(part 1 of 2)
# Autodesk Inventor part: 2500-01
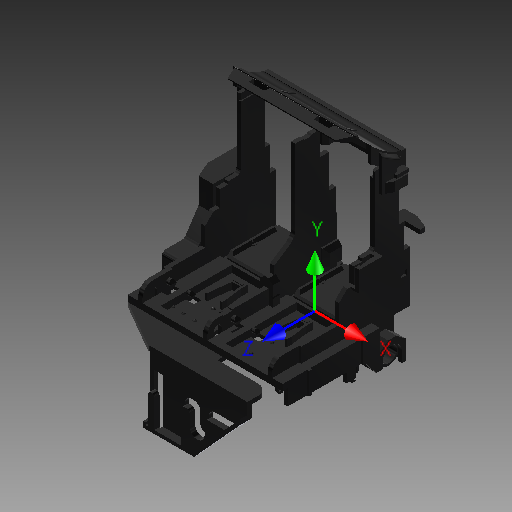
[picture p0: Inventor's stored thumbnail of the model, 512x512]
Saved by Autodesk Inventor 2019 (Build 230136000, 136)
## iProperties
Company: Autodesk Inc.
Created: 2006-01
Part Number: 2500-01
Document SubType Name: Modeling
Designer: Autodesk Inc.
Density: 1.06 g/cm^3
Mass: 41.9932 g
Surface Area: 433.717 cm^2
Volume: 39.6162 cm^3
Material: ABS Plastic
Appearance: Smooth - Black
Description: CARTRIDGE SEAT BLOCK
Author: Inventor
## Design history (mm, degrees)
sketch "Sketch1"
  geometry: L1 (0, 61.8)-(0, -3.3) reference; L2 (-6.86, 0)-(18.06, 0) reference; L3 (-3.3, 6)-(14.5, 6); L4 (14.5, 6)-(14.5, 52.5); L5 (14.5, 52.5)-(9.5, 52.5); L6 (9.5, 52.5)-(9.5, 50); L7 (9.5, 50)-(4, 50); L8 (4, 50)-(4, 21.9); L9 (4, 21.9)-(-0.5, 21.9); L10 (-0.5, 21.9)-(-0.5, 17.2); L11 (-0.5, 17.2)-(4, 17.2); L12 (4, 17.2)-(4, 13.3); L13 (4, 13.3)-(-3.3, 7.7); L14 (-3.3, 6)-(-3.3, 7.7)
  constraints: 24 end point, 6 parallel, 5 perpendicular, 1 collinear
  dimensions: "d2" = 6 distance between parallel lines of L3 L2; "d3" = 5 distance of L4.end L5.end; "d4" = 10.5 distance between parallel lines of L4 L8; "d5" = 4 distance between parallel lines of L8 L1; "d6" = 2.5 distance between parallel lines of L5 L7; "d8" = 52.5 distance between parallel lines of L5 L2; "d9" = 4.7 distance of L9.end L10.end; "d10" = 4.5 distance of L8.end L9.end; "d11" = 17.2 distance between parallel lines of L11 L2; "d12" = 17.8 distance between parallel lines of L4 L14; "d13" = 1.7 distance from line of L13.end L3; "d15" = 13.3 distance from line of L12.end L2
extrude "Extrusion1" new body sketch "Sketch1" stored distance "d16" = 74; taper "d17" = 0 deg
sketch "Sketch2"
  geometry: L1 (0, -46.5)-(74, -46.5) reference; L2 (37, -56.792)-(37, 10.66); L3 (27.5, -43.3)-(12.5, -43.3); L4 (12.5, -43.3)-(12.5, -9.3); L5 (12.5, -9.3)-(30.5, -9.3); L6 (30.5, -9.3)-(30.5, -36.3); L7 (27.5, -43.3)-(27.5, -38.5); L8 (29.7, -36.3)-(30.5, -36.3); A1 r 2.2 centre (29.7, -38.5) between (29.7, -36.3) and (27.5, -38.5); 1 further point
  constraints: 14 end point, 3 parallel, 3 perpendicular, 2 point on circle, 2 tangent, 1 centre point, 1 horizontal, 1 midpoint, 1 point on line
  dimensions: "d19" = 15 distance of L3.start L3.end; "d20" = 18 distance of L4.end L5.end; "d22" = 34 distance between parallel lines of L5 L3; "d23" = 27 distance between parallel lines of L5 L8; "d24" = 6.5 distance between parallel lines of L6 L2; "d25" = 3.2 distance between parallel lines of L1 L3; "d26" = 2.2 radius of A1
extrude "Extrusion2" cut sketch "Sketch2" distance "d27" = 3.3; taper "d28" = 0 deg
pattern_linear "Rectangular Pattern1" dims "d31" = 31
shell "Shell1" dims "d18" = 1.6
sketch "Sketch10"
  geometry: L1 (0, 0)-(74, 0) reference; L2 (0, -46.5)-(74, -46.5) reference; L3 (70, 0)-(4, 0); L4 (4, 0)-(4, 18.5); L5 (4, 18.5)-(70, 18.5); L6 (70, 18.5)-(70, 0); L7 (37, 31.5)-(37, -59.5) reference
  constraints: 8 end point, 2 parallel, 1 horizontal, 1 perpendicular, 1 point on line, 1 other
  dimensions: "d104" = 66 distance of L3.start L3.end; "d106" = 65 distance between parallel lines of L2 L5
extrude "Extrusion10" join sketch "Sketch10" distance "d107" = 2; taper "d108" = 0 deg
sketch "Sketch3"
  geometry: L1 (0, 0)-(74, 0) reference; L2 (1.6, -1.6)-(72.4, -1.6) reference; L3 (0, 0)-(23.5, 13.58); L4 (23.5, 13.58)-(70, 13.58); L5 (70, 13.58)-(70, 7.58); L6 (65, 2.58)-(45.5, 2.58); L7 (45.5, 2.58)-(45.5, 0); L8 (0, 0)-(45.5, 0); A1 r 5 centre (65, 7.58) between (65, 2.58) and (70, 7.58); 1 further point
  constraints: 12 end point, 3 perpendicular, 3 point on line, 2 point on circle, 2 tangent, 1 centre point, 1 collinear, 1 parallel
  dimensions: "d32" = 46.5 distance of L3.end L4.end; "d33" = 70 distance from line of L5 L1.start; "d34" = 11 distance of L4.end point (70, 2.58); "d35" = 13.58 distance between parallel lines of L1 L4; "d36" = 45.5 distance from line of L7 L1.start; "d37" = 5 radius of A1
extrude "Extrusion3" join sketch "Sketch3" distance "d38" = 2; taper "d39" = 0 deg
sketch "Sketch4"
  geometry: L1 (46.5, 2)-(0, 2) reference; L2 (0, 0)-(0, 2) reference; L3 (46.5, 0)-(0, 0) reference; L4 (46.5, 0)-(46.5, 2) reference; L5 (46.5, 2)-(46.5, -5.8); L6 (46.5, -5.8)-(24.5, -30); L7 (24.5, -30)-(0, -30); L8 (0, 0)-(0, -30)
  constraints: 8 end point, 2 perpendicular, 1 collinear
  dimensions: "d40" = 30 distance of L2.start L7.end; "d41" = 24.5 distance of L6.end L7.end; "d42" = 7.8 distance of L1.start L5.end
extrude "Extrusion4" join sketch "Sketch4" stored distance "d43" = 5.5; taper "d44" = 0 deg
sketch "Sketch5"
  geometry: L1 (-24.5, -30)-(-46.5, -5.8) reference; L2 (0, -30)-(-24.5, -30) reference; L3 (0, 0)-(0, -30) reference; L4 (-42.682, -10)-(-31, -10); L5 (-28, -13)-(-28, -18.5); L6 (-26, -20.5)-(-26, -20.5); L7 (-24, -18.5)-(-24, -13); L8 (-21, -10)-(-19.7, -10); L9 (-16.7, -13)-(-16.7, -30); L10 (-2, -30)-(-2, -7); L11 (-2, -7)-(-6, -7); L12 (-6, -7)-(-6, -30); L13 (-2, -30)-(-6, -30); A1 r 3 centre (-19.7, -13) between (-16.7, -13) and (-19.7, -10); A2 r 3 centre (-21, -13) between (-21, -10) and (-24, -13); A3 r 2 centre (-26, -18.5) between (-26, -20.5) and (-24, -18.5); A4 r 2 centre (-26, -18.5) between (-28, -18.5) and (-26, -20.5); A5 r 3 centre (-31, -13) between (-28, -13) and (-31, -10); 5 further points
  constraints: 20 end point, 14 point on line, 10 point on circle, 10 tangent, 5 centre point, 5 perpendicular, 3 collinear, 3 equal radius, 3 parallel
  dimensions: "d45" = 4 distance between parallel lines of L10 L12; "d46" = 23 distance of L10.start L10.end; "d47" = 20 distance of point (-16.7, -10) L9.end; "d48" = 7.3 distance of point (-24, -10) point (-16.7, -10); "d49" = 4 distance of point (-28, -20.5) point (-24, -20.5); "d50" = 10.7 distance between parallel lines of L9 L12; "d51" = 10.5 distance of point (-28, -10) point (-28, -20.5); "d52" = 2 distance between parallel lines of L3 L10; "d53" = 3 radius of A1; "d54" = 2 radius of A3
extrude "Extrusion5" cut sketch "Sketch5" distance "d55" = 3; taper "d56" = 0 deg
sketch "Sketch6"
  geometry: L1 (-42.682, -10)-(-31, -10) reference; L2 (-28, -13)-(-28, -18.5) reference; L3 (-24, -18.5)-(-24, -13) reference; L4 (-21, -10)-(-19.7, -10) reference; L5 (-16.7, -13)-(-16.7, -30) reference; L6 (-6, -30)-(-6, -7) reference; L7 (-6, -7)-(-2, -7) reference; L8 (-2, -7)-(-2, -30) reference; L9 (-46.5, -5.8)-(-46.5, 0) reference; L10 (-42.682, -10)-(-46.5, -5.8) reference; L11 (-40.519, -10)-(-39.065, -11.6); L12 (-39.065, -11.6)-(-31.1, -11.6); L13 (-29.6, -18.5)-(-29.6, -13.1); L14 (-22.4, -18.5)-(-22.4, -13.1); L15 (-18.3, -28.4)-(-16.7, -28.4); L16 (-18.3, -28.4)-(-18.3, -13.1); L17 (-19.8, -11.6)-(-20.9, -11.6); L18 (-27.997, -21.496)-(-28, -21.496); L19 (-24.5, -30)-(-42.682, -10) reference; L20 (-16.7, -30)-(-24.5, -30) reference; L21 (-2.5, -28.4)-(-2.5, -15); L22 (-4, -13.5)-(-4, -13.5); L23 (-5.5, -15)-(-5.5, -28.4); L24 (-6, -28.4)-(-6, -7.5); L25 (-6, -7.5)-(-2, -7.5); L26 (-2, -7.5)-(-2, -28.4); L27 (-2, -30)-(-6, -30) reference; L28 (-2, -28.4)-(-2.5, -28.4); L29 (-5.5, -28.4)-(-6, -28.4); A1 r 3 centre (-31, -13) between (-28, -13) and (-31, -10) reference; A2 r 2 centre (-26, -18.5) between (-28, -18.5) and (-24, -18.5) reference; A3 r 3 centre (-21, -13) between (-21, -10) and (-24, -13) reference; A4 r 3 centre (-19.7, -13) between (-16.7, -13) and (-19.7, -10) reference; A5 r 3.6 centre (-26, -18.5) between (-29.6, -18.5) and (-22.4, -18.5); A6 r 1.5 centre (-4, -15) between (-2.5, -15) and (-4, -13.5); A7 r 1.5 centre (-4, -15) between (-4, -13.5) and (-5.5, -15); A8 r 1.5 centre (-19.8, -13.1) between (-18.3, -13.1) and (-19.8, -11.6); A9 r 1.5 centre (-20.9, -13.1) between (-20.9, -11.6) and (-22.4, -13.1); A10 r 1.5 centre (-31.1, -13.1) between (-29.6, -13.1) and (-31.1, -11.6)
  constraints: 32 end point, 13 point on circle, 12 tangent, 10 perpendicular, 6 centre point, 5 parallel, 5 point on line, 4 equal radius, 3 collinear, 1 coincident
  dimensions: "d57" = 1.6 distance between parallel lines of L5 L16; "d58" = 1.6 distance between parallel lines of L17 L4 (= d57); "d59" = 1.6 distance between parallel lines of L3 L14 (= d57); "d60" = 1.6 distance between parallel lines of L13 L2 (= d57); "d61" = 1.6 distance between parallel lines of L1 L12 (= d57); "d62" = 1.6 distance between parallel lines of L19 L11 (= d57); "d63" = 1.6 distance between parallel lines of L20 L15 (= d57); "d64" = 0.5 distance between parallel lines of L6 L23; "d65" = 0.5 distance between parallel lines of L7 L25; "d66" = 16.5 distance between parallel lines of L27 L22; "d67" = 1.5 radius of A6
extrude "Extrusion6" cut sketch "Sketch6" extent not by distance; stored distance "d68" = 3; taper "d69" = 0 deg
sketch "Sketch7"
  geometry: L1 (2, -28.4)-(2, -7.5) reference; L2 (2, -7.5)-(6, -7.5) reference; L3 (6, -7.5)-(6, -28.4) reference; L4 (16.7, -28.4)-(16.7, -13) reference; L5 (19.7, -10)-(21, -10) reference; L6 (24, -13)-(24, -18.5) reference; L7 (28, -18.5)-(28, -13) reference; L8 (31, -10)-(40.519, -10) reference; L9 (0, -30)-(0, 2) reference; L10 (46.5, -5.8)-(24.5, -30) reference; L11 (46.5, 2)-(46.5, -5.8) reference; L12 (0, 2)-(46.5, 2) reference; L13 (16.7, -28.4)-(6, -28.4); L14 (2, -28.4)-(1.2, -28.4); L15 (1.2, -28.4)-(1.2, -27.4); L16 (1.2, -27.4)-(0, -27.4); L17 (0, -27.4)-(0, 2); L18 (40.519, -10)-(46.5, -3.421); A1 r 3 centre (19.7, -13) between (19.7, -10) and (16.7, -13) reference; A2 r 3 centre (21, -13) between (24, -13) and (21, -10) reference; A3 r 2 centre (26, -18.5) between (24, -18.5) and (28, -18.5) reference; A4 r 3 centre (31, -13) between (31, -10) and (28, -13) reference
  constraints: 12 end point, 2 collinear, 2 parallel, 2 perpendicular, 2 point on line
  dimensions: "d70" = 1 distance of L14.end L15.end; "d71" = 1.2 distance of L15.end L16.end
extrude "Extrusion7" cut sketch "Sketch7" distance "d72" = 3.5; taper "d73" = 0 deg
sketch "Sketch8"
  geometry: L1 (9.607, 52.5)-(16.5, 52.5); L2 (24.5, 20.5)-(29.5, 20.5); L3 (29.5, 20.5)-(34.682, 12.726); L4 (38.843, 10.5)-(75, 10.5); L5 (75, 10.5)-(75, 6.5); L6 (75, 6.5)-(74.4, 6.1); L7 (74.4, 6.1)-(74.4, 2.9); L8 (74.4, 2.9)-(75, 2.5); L9 (75, 2.5)-(75, -1.5); L10 (75, -1.5)-(63.5, -1.5); L11 (63.5, -1.5)-(63.5, -5.8); L12 (63.5, -5.8)-(47.5, -5.8); L13 (47.5, -5.8)-(47.5, -9.15); L14 (47.5, -9.15)-(36.5, -9.15); L15 (36.5, -9.15)-(36.5, -9.5); L16 (36.5, -9.5)-(9.607, -9.5); L17 (9.607, -9.5)-(9.607, 52.5); L18 (50.827, 4.5)-(44.324, 4.5); L19 (14.5, 52.5)-(14.5, 6) reference; L20 (14.5, 6)-(-3.3, 6) reference; L21 (9.5, 52.5)-(14.5, 52.5) reference; L22 (21.5, 45)-(20.9, 45); L23 (20.9, 45)-(20.9, 40.5); L24 (20.9, 40.5)-(21.5, 40.5); L25 (21.5, 47.5)-(21.5, 45); L26 (21.5, 40.5)-(21.5, 23.5); L27 (9.5, 66.08)-(11.5, 66.08) reference; L28 (14.5, -12.5)-(12.5, -12.5) reference; A1 r 5 centre (16.5, 47.5) between (21.5, 47.5) and (16.5, 52.5); A2 r 3 centre (24.5, 23.5) between (21.5, 23.5) and (24.5, 20.5); A3 r 5 centre (38.843, 15.5) between (34.682, 12.726) and (38.843, 10.5)
  constraints: 46 end point, 19 parallel, 7 perpendicular, 6 point on circle, 6 tangent, 4 collinear, 3 centre point, 1 horizontal, 1 vertical, 1 other
  dimensions: "d75" = 27 distance between parallel lines of L15 L11; "d76" = 3.2 distance of L6.end L7.end; "d77" = 4 distance of L8.end L5.end; "d78" = 12 distance between parallel lines of L10 L4; "d80" = 0.35 distance between parallel lines of L16 L14; "d82" = 20 distance between parallel lines of L16 L4; "d83" = 4.3 distance of L10.end L11.end; "d84" = 11.5 distance of L9.end L10.end; "d85" = 33 distance between parallel lines of L13 L19; "d86" = 60.5 distance between parallel lines of L19 L9; "d87" = 0.6 distance between parallel lines of L7 L5; "d89" = 30 distance between parallel lines of L16 L2; "d91" = 15 distance from line of L19 L2.end; "d92" = 0.6 distance of L23.end L24.end; "d93" = 7 distance between parallel lines of L19 L25; "d94" = 7.5 distance from line of L22.end L1; "d95" = 4.5 distance of L23.end L22.end; "d96" = 5 radius of A1; "d97" = 3 radius of A2; "d98" = 5 radius of A3; "d109" = 3 distance between parallel lines of L28 L16
extrude "Extrusion8" join sketch "Sketch8" stored distance "d99" = 2; taper "d100" = 0 deg
sketch "Sketch9"
  geometry: L1 (16.5, 49.5)-(9.5, 49.5); L2 (16.5, 45.5)-(9.5, 45.5); L3 (9.5, 49.5)-(9.5, 45.5); L4 (9.5, 66.08)-(9.5, 52.5) reference; A1 r 2 centre (16.5, 47.5) between (16.5, 45.5) and (16.5, 49.5); A2 r 5 centre (16.5, 47.5) between (21.5, 47.5) and (16.5, 52.5) reference
  constraints: 6 end point, 2 point on circle, 2 tangent, 1 centre point, 1 collinear, 1 concentric, 1 horizontal, 1 parallel, 1 perpendicular
  dimensions: "d101" = 4 distance between parallel lines of L2 L1
extrude "Extrusion9" cut sketch "Sketch9" stored distance "d102" = 10; taper "d103" = 0 deg
sketch "Sketch11"
  geometry: L1 (-33.1, 9.2)-(-40.9, 9.2); L2 (-40.9, 9.2)-(-40.9, 14.8); L3 (-40.9, 14.8)-(-33.1, 14.8); L4 (-33.1, 14.8)-(-33.1, 9.2); L5 (-37, 81.266)-(-37, -32.596) reference; 1 further point
  constraints: 8 end point, 2 parallel, 1 horizontal, 1 perpendicular, 1 other
  dimensions: "d110" = 7.8 distance of L2.end L3.end; "d111" = 5.6 distance of L1.end L2.end; "d112" = 2.2 distance from line of L1 point (-38, 7)
extrude "Extrusion11" cut sketch "Sketch11" distance "d113" = 2; taper "d114" = 0 deg
sketch "Sketch12"
  geometry: L1 (-40.9, 14.8)-(-38, 14.8) reference; L2 (-34, 29.3)-(-40, 29.3); L3 (-40, 29.3)-(-40, 32.8); L4 (-40, 32.8)-(-34, 32.8); L5 (-34, 32.8)-(-34, 29.3); L6 (-37, 81.266)-(-37, -32.596) reference
  constraints: 8 end point, 2 parallel, 1 horizontal, 1 perpendicular, 1 other
  dimensions: "d115" = 6 distance of L2.start L2.end; "d116" = 3.5 distance of L2.end L3.end; "d117" = 14.5 distance between parallel lines of L2 L1
extrude "Extrusion12" join sketch "Sketch12" distance "d118" = 11.2; taper "d119" = 0 deg
chamfer "Chamfer1" distance "d120" = 2; stored, may be unused: second distance "d121" = 2, angle "d122" = 45 deg
sketch "Sketch13"
  geometry: L1 (0, 0)-(0, -22) reference; L2 (-0.8, -10.7)-(2.8, -10.7); L3 (2.8, -10.7)-(4.5, -12.6); L4 (4.5, -12.6)-(4.5, -18.2); L5 (4.5, -18.2)-(-2.5, -18.2); L6 (-2.5, -18.2)-(-2.5, -12.6); L7 (-2.5, -12.6)-(-0.8, -10.7); L8 (1, -76.1)-(1, 57.6) reference; L9 (38, -22)-(2, -22) reference
  constraints: 12 end point, 3 perpendicular, 1 parallel, 2 other
  dimensions: "d123" = 7.5 distance between parallel lines of L5 L2; "d124" = 7 distance of L4.end L5.end; "d125" = 5.6 distance of L3.end L4.end; "d126" = 3.6 distance of L2.start L2.end; "d127" = 3.8 distance between parallel lines of L9 L5
extrude "Extrusion13" join sketch "Sketch13" distance "d128" = 7.8; taper "d129" = 0 deg
chamfer "Chamfer2" distance "d130" = 1.8; stored, may be unused: second distance "d131" = 2, angle "d132" = 45 deg
sketch "Sketch14"
  geometry: L1 (4.5, -18.2)-(2, -18.2) reference; L2 (4.5, -12.6)-(4.5, -18.2) reference; L3 (2.8, -10.7)-(4.5, -12.6) reference; L4 (2, -10.7)-(2.8, -10.7) reference; L5 (-0.8, -10.7)-(0, -10.7) reference; L6 (-2.5, -12.6)-(-0.8, -10.7) reference; L7 (-2.5, -18.2)-(-2.5, -12.6) reference; L8 (0, -18.2)-(-2.5, -18.2) reference; L9 (-0.353, -11.7)-(2.353, -11.7); L10 (2.353, -11.7)-(3.5, -12.982); L11 (3.5, -12.982)-(3.5, -17.2); L12 (3.5, -17.2)-(-1.5, -17.2); L13 (-1.5, -17.2)-(-1.5, -12.982); L14 (-1.5, -12.982)-(-0.353, -11.7)
  constraints: 12 end point, 8 parallel, 1 perpendicular
  dimensions: "d133" = 1 distance between parallel lines of L4 L9; "d134" = 1 distance between parallel lines of L3 L10; "d135" = 1 distance between parallel lines of L2 L11 (= d133); "d136" = 1 distance between parallel lines of L1 L12 (= d133); "d137" = 1 distance between parallel lines of L7 L13 (= d133); "d138" = 1 distance between parallel lines of L6 L14 (= d133)
extrude "Extrusion14" cut sketch "Sketch14" distance "d139" = 5.6; taper "d140" = 0 deg
sketch "Sketch15"
  geometry: L1 (2, -4)-(0, -4) reference; L2 (2.7, 0)-(-0.7, 0); L3 (-0.7, 0)-(-2.5, 1.8); L4 (-2.5, 1.8)-(-2.5, 7); L5 (-2.5, 7)-(-1.15, 7); L6 (-1.15, 7)-(-1.15, 3.7); L7 (-1.15, 3.7)-(3.15, 3.7); L8 (3.15, 3.7)-(3.15, 7); L9 (3.15, 7)-(4.5, 7); L10 (4.5, 7)-(4.5, 1.8); L11 (4.5, 1.8)-(2.7, 0); L12 (2, -7.5)-(34, -7.5) reference; L13 (1, 27.266)-(1, -86.596) reference; L14 (2, -12)-(0, -12) reference
  constraints: 20 end point, 7 parallel, 1 collinear, 1 perpendicular, 3 other
  dimensions: "d141" = 4.3 distance between parallel lines of L6 L8; "d142" = 7 distance between parallel lines of L4 L10; "d143" = 19 distance between parallel lines of L5 L14; "d144" = 3.3 distance of L7.end L8.end; "d145" = 7 distance between parallel lines of L5 L2; "d146" = 45 deg angle of L2 L3; "d147" = 1.80005 horizontal distance of L2.end L3.end
extrude "Extrusion15" join sketch "Sketch15" distance "d148" = 6; taper "d149" = 0 deg
workplane "Work Plane1"
sketch "Sketch16"
  geometry: L1 (16.5, 52.5)-(14.5, 52.5); L2 (21.5, 47.5)-(21.5, 38); L3 (21.5, 38)-(14.5, 38); L4 (14.5, 38)-(14.5, 52.5); L5 (14.5, 6)-(14.5, 52.5) reference; A1 r 5 centre (16.5, 47.5) between (21.5, 47.5) and (16.5, 52.5) reference
  constraints: 8 end point, 2 perpendicular, 2 tangent, 1 collinear, 1 horizontal
  dimensions: "d151" = 14.5 distance between parallel lines of L3 L1
extrude "Extrusion16" join sketch "Sketch16" distance "d152" = 2; taper "d153" = 0 deg
sketch "Sketch17" dims "d59" = 1.6 (= d57), "d197" = 1.8, "d441" = 1, "d458" = 7.5, "d465" = 0, "d472" = 1.5, "d576" = 1, "d599" = 0.5
  geometry: L1 (52.5, 16.5)-(52.5, 14.5) reference; L2 (38, 21.5)-(47.5, 21.5) reference; L3 (38, 14.5)-(38, 21.5) reference; L4 (52.5, 14.5)-(38, 14.5) reference; L5 (39.6, 21.5)-(21.5, 21.5); L6 (21.5, 21.5)-(21.5, 30.5); L7 (21.5, 30.5)-(17.5, 34.5); L8 (17.5, 34.5)-(14.5, 34.5); L9 (14.5, 34.5)-(14.5, 42.2); L10 (14.5, 42.2)-(10.5, 42.2); L11 (10.5, 42.2)-(10.5, 43.5); L12 (10.5, 43.5)-(6.5, 43.5); L13 (4.5, 45.5)-(4.5, 76.5); L14 (4.5, 76.5)-(-9.5, 76.5); L15 (-9.5, 76.5)-(-9.5, 69); L16 (-9.5, 69)-(-7.2, 69); L17 (-7.2, 69)-(-7.2, 48.8); L18 (-7.2, 48.8)-(-9.5, 48.8); L19 (-9.5, 48.8)-(-9.5, 37); L20 (-9.5, 37)-(-12.5, 37); L21 (-12.5, 37)-(-12.5, 12.5); L22 (39.6, 21.5)-(39.6, 12.5); L23 (40.574, 12.5)-(-12.5, 12.5); L24 (-12.5, 14.5)-(-12.5, 12.5) reference; L25 (-9.5, 9.607)-(6, 9.607) reference; L26 (-12.5, 12.5)-(6, 12.5) reference; A1 r 2 centre (6.5, 45.5) between (4.5, 45.5) and (6.5, 43.5); 1 further point
  constraints: 38 end point, 16 parallel, 4 point on line, 3 perpendicular, 2 collinear, 2 point on circle, 2 tangent, 1 centre point
  dimensions: "d154" = 1.6 distance between parallel lines of L3 L22; "d155" = 14 distance of L13.end L14.end; "d156" = 2.3 distance between parallel lines of L15 L17; "d158" = 3 distance between parallel lines of L21 L19; "d159" = 34 distance between parallel lines of L21 L6; "d160" = 13 distance from line of L13 L7.end; "d161" = 20 distance from line of L11.end L19; "d162" = 45 deg angle of L6 L7; "d163" = 4 horizontal distance of L6.end L7.end; "d164" = 64 distance between parallel lines of L14 L23; "d165" = 24.5 distance between parallel lines of L23 L20; "d166" = 36.3 distance between parallel lines of L23 L18; "d167" = 7.5 distance between parallel lines of L16 L14; "d168" = 33 distance of point (4.5, 43.5) L13.end; "d169" = 1.3 distance from line of L10 L11.end; "d170" = 9 distance between parallel lines of L12 L8; "d171" = 4 distance of L9.end L10.end; "d266" = 2 radius of A1
extrude "Extrusion17" join sketch "Sketch17" stored distance "d172" = 2; taper "d173" = 0 deg
sketch "Sketch18"
  geometry: L1 (-47.5, 21.5)-(-38, 21.5) reference; L2 (-49.5, 16.5)-(-49.5, 12.9); L3 (-49.5, 12.9)-(-45.5, 12.9); L4 (-45.5, 12.9)-(-45.5, 16.5); L5 (-7.6, 12.9)-(-50.9, 12.9) reference; A1 r 2 centre (-47.5, 16.5) between (-45.5, 16.5) and (-49.5, 16.5) reference
  constraints: 6 end point, 2 perpendicular, 2 tangent, 1 collinear, 1 parallel
extrude "Extrusion18" cut sketch "Sketch18" distance "d174" = 1; taper "d175" = 0 deg
sketch "Sketch19"
  geometry: L1 (-67, 14.5)-(-67, 7) reference; L2 (-38, 9.2)-(-40.9, 9.2) reference; L3 (-67, 9.2)-(-64.2, 9.2); L4 (-64.2, 9.2)-(-64.2, 14.8); L5 (-64.2, 14.8)-(-67, 14.8); L6 (-67, 14.8)-(-67, 9.2)
  constraints: 8 end point, 2 parallel, 1 collinear, 1 horizontal, 1 perpendicular, 1 point on line
  dimensions: "d176" = 2.8 distance of L4.end L5.end; "d177" = 5.6 distance of L3.end L4.end
extrude "Extrusion19" cut sketch "Sketch19" extent not by distance; stored distance "d178" = 1; taper "d179" = 0 deg
sketch "Sketch20"
  geometry: L1 (12.5, -43.3)-(27.5, -43.3) reference; L2 (30.5, -36.3)-(30.5, -9.3) reference; L3 (12.5, -9.3)-(12.5, -43.3) reference; L4 (12.5, -31.3)-(16.5, -31.3); L5 (16.5, -31.3)-(16.5, -27.8); L6 (16.5, -27.8)-(12.5, -27.8); L7 (12.5, -27.8)-(12.5, -31.3); L8 (30.5, -31.3)-(26.5, -31.3); L9 (26.5, -31.3)-(26.5, -27.8); L10 (26.5, -27.8)-(30.5, -27.8); L11 (30.5, -27.8)-(30.5, -31.3)
  constraints: 16 end point, 4 parallel, 3 collinear, 2 horizontal, 2 perpendicular, 2 point on line
  dimensions: "d180" = 4 distance of L5.end L6.end; "d181" = 3.5 distance of L4.end L5.end; "d182" = 12 distance between parallel lines of L1 L4
extrude "Extrusion20" cut sketch "Sketch20" extent not by distance; stored distance "d183" = 1; taper "d184" = 0 deg
sketch "Sketch21"
  geometry: L1 (30.5, -9.3)-(12.5, -9.3) reference; L2 (30.5, -36.3)-(30.5, -31.3) reference; L3 (21.5, -45.632)-(21.5, -3.603); L4 (18.5, -27)-(18.5, -24.565); L5 (18.5, -24.565)-(19.6, -16.2); L6 (19.6, -16.2)-(21.5, -16.2); L7 (21.5, -13.3)-(18.5, -13.3); L8 (18.5, -13.3)-(18.5, -16.895); L9 (18.5, -16.895)-(17.5, -24.5); L10 (17.5, -24.5)-(17.5, -27); L11 (17.5, -27)-(18.5, -27); L12 (25.5, -27)-(24.5, -27); L13 (24.5, -27)-(24.5, -24.565); L14 (23.4, -16.2)-(21.5, -16.2); L15 (24.5, -24.565)-(23.4, -16.2); L16 (24.5, -16.895)-(25.5, -24.5); L17 (24.5, -13.3)-(24.5, -16.895); L18 (21.5, -13.3)-(24.5, -13.3); L19 (25.5, -24.5)-(25.5, -27); 1 further point
  constraints: 34 end point, 7 symmetric about line, 6 parallel, 3 point on line, 2 perpendicular, 1 midpoint
  dimensions: "d185" = 1 distance between parallel lines of L10 L4; "d186" = 6 distance between parallel lines of L8 L17; "d187" = 3.8 distance of L5.end L14.start; "d188" = 13.7 distance between parallel lines of L7 L11; "d189" = 2.9 distance between parallel lines of L7 L6; "d190" = 4 distance between parallel lines of L1 L7; "d191" = 6 distance between parallel lines of L4 L13; "d193" = 2.5 distance of L9.end L10.end; "d194" = 1 distance between parallel lines of L9 L5 (= d185)
extrude "Extrusion21" join sketch "Sketch21" stored distance "d195" = 1; taper "d196" = 0 deg
sketch "Sketch22"
  geometry: L1 (-61.5, 37.2)-(-43.5, 37.2) reference; L2 (-38, 32.8)-(-38, 62) reference; L3 (-68, 65)-(-68, 14.5) reference; L4 (-38, 38.2)-(-68, 38.2); L5 (-68, 38.2)-(-68, 39); L6 (-66.8, 40)-(-39.2, 40); L7 (-38, 39)-(-38, 38.2); L8 (-68, 38.2)-(-66.8, 38.2); L9 (-66.8, 40)-(-66.8, 44.2); L10 (-66.8, 44.2)-(-68, 44.2); L11 (-68, 44.2)-(-68, 38.2); L12 (-38, 38.2)-(-39.2, 38.2); L13 (-39.2, 40)-(-39.2, 44.2); L14 (-39.2, 44.2)-(-38, 44.2); L15 (-38, 44.2)-(-38, 38.2)
  constraints: 24 end point, 6 parallel, 3 collinear, 3 horizontal, 3 perpendicular, 2 point on line
  dimensions: "d197" = 1.8 distance between parallel lines of L4 L6; "d198" = 6 distance between parallel lines of L10 L4; "d199" = 1.2 distance between parallel lines of L11 L9; "d202" = 1 distance between parallel lines of L4 L1
extrude "Extrusion22" cut sketch "Sketch22" distance "d200" = 1.5; taper "d201" = 0 deg
sketch "Sketch23"
  geometry: L1 (-4, 65)-(-68, 65) reference; L2 (-39.2, 44.2)-(-38, 44.2); L3 (-38, 44.2)-(-38, 65); L4 (-38, 65)-(-39.2, 65); L5 (-39.2, 65)-(-39.2, 44.2); L6 (-66.8, 44.2)-(-68, 44.2); L7 (-68, 44.2)-(-68, 65); L8 (-68, 65)-(-66.8, 65); L9 (-66.8, 65)-(-66.8, 44.2); L10 (-38, 54)-(-38, 50) reference
  constraints: 16 end point, 4 parallel, 2 horizontal, 2 perpendicular, 1 collinear, 1 point on line
extrude "Extrusion23" cut sketch "Sketch23" distance "d203" = 0.6; taper "d204" = 0 deg
sketch "Sketch24"
  geometry: L1 (0, 0)-(0, -25) reference; L2 (0, -25)-(2.2, -25); L3 (2.2, -25)-(2.2, -3); L4 (2.2, -3)-(0, -3); L5 (0, -3)-(0, -25); L6 (27.6, -25)-(25.4, -25); L7 (25.4, -25)-(25.4, -3); L8 (25.4, -3)-(27.6, -3); L9 (27.6, -3)-(27.6, -25)
  constraints: 16 end point, 4 parallel, 2 collinear, 2 horizontal, 2 perpendicular
  dimensions: "d205" = 22 distance of L2.end L3.end; "d206" = 2.2 distance between parallel lines of L1 L3
extrude "Extrusion24" join sketch "Sketch24" distance "d207" = 1.2; taper "d208" = 0 deg
chamfer "Chamfer3" distance "d209" = 2; stored, may be unused: second distance "d210" = 2, angle "d211" = 45 deg
chamfer "Chamfer5" distance "d215" = 1.2; stored, may be unused: second distance "d216" = 2, angle "d217" = 30 deg
sketch "Sketch25"
  geometry: L1 (27.6, 0)-(0, 0) reference; L2 (2.2, -3)-(2.2, -24.2) reference; L3 (27.6, -12.326)-(27.6, -14.874); L4 (0, -14.874)-(0, -12.326); L5 (0, -20.8)-(0, 0) reference; L6 (27.6, 0)-(27.6, -20.8) reference; A1 r 1.75 centre (1.2, -13.6) between (0, -14.874) and (0, -12.326); A2 r 1.75 centre (26.4, -13.6) between (27.6, -12.326) and (27.6, -14.874)
  constraints: 4 end point, 4 point on circle, 2 centre point, 2 collinear, 2 parallel, 2 point on line, 1 equal radius, 1 horizontal alignment
  dimensions: "d219" = 3.5 diameter of A1; "d220" = 13.6 distance from line of L1 A1.centre; "d221" = 1.2 distance from line of L5 A1.centre; "d222" = 1.2 distance from line of L6 A2.centre
extrude "Extrusion25" join sketch "Sketch25" distance "d223" = 0.2; taper "d224" = 0 deg
mirror "Mirror1"
workplane "Work Plane2"
sketch "Sketch26"
  geometry: L1 (32.388, 7.5)-(-7.372, 7.5); L2 (2.5, 7.5)-(0, 7.5); L3 (0, 7.5)-(0, 6.15); L4 (0, 6.15)-(2.5, 6.15); L5 (2.5, 6.15)-(2.5, 7.5); L6 (81.874, 47.5)-(-22.246, 47.5) reference; L7 (30, 76.266)-(30, -37.596) reference; L8 (0, 0)-(0, 9.5) reference; L9 (29, 7.5)-(26.5, 7.5); L10 (26.5, 7.5)-(26.5, 6.15); L11 (26.5, 6.15)-(29, 6.15); L12 (29, 6.15)-(29, 7.5); L13 (29, 7)-(29, 2.5) reference
  constraints: 18 end point, 4 collinear, 4 parallel, 3 horizontal, 2 perpendicular, 2 point on line
  dimensions: "d226" = 40 distance between parallel lines of L6 L1; "d227" = 2.7 diameter of L4 L1; "d228" = 2.5 distance of L3.end L4.end
revolve "Revolution1" sketch "Sketch26" stored, may be unused: angle "d229" = 90 deg
workplane "Work Plane3"
sketch "Sketch27"
  geometry: L1 (-2.559, 13.5)-(-28.388, 13.5); L2 (1, 78.266)-(1, -35.596) reference; L3 (52.8, 49.5)-(-50.8, 49.5) reference; L4 (-21, 13.5)-(-23.5, 13.5); L5 (-23.5, 13.5)-(-23.5, 12.5); L6 (-23.5, 12.5)-(-21, 12.5); L7 (-21, 12.5)-(-21, 13.5); L8 (-5.5, 13.5)-(-8, 13.5); L9 (-8, 13.5)-(-8, 12.5); L10 (-8, 12.5)-(-5.5, 12.5); L11 (-5.5, 12.5)-(-5.5, 13.5); L12 (-23.5, 0.2)-(-23.5, 34.2) reference; L13 (-5.5, 34.2)-(-5.5, 7.2) reference
  constraints: 18 end point, 4 collinear, 4 parallel, 3 horizontal, 2 perpendicular, 2 point on line
  dimensions: "d231" = 36 distance between parallel lines of L3 L1; "d232" = 2.5 distance of L5.end L6.end; "d233" = 2 diameter of L6 L1
revolve "Revolution2" sketch "Sketch27" stored, may be unused: angle "d234" = 90 deg
workplane "Work Plane4"
sketch "Sketch28"
  geometry: L1 (1, -23)-(0, -23); L2 (1.2, -14.1)-(1.2, -13.1); L3 (26.4, -14.1)-(26.4, -13.1); A1 r 1.75 centre (1.2, -13.6) between (2, -15.156) and (2, -12.044) reference; A2 r 0.5 centre (1.2, -13.6) between (1.2, -14.1) and (1.2, -13.1); A3 r 0.5 centre (26.4, -13.6) between (26.4, -13.1) and (26.4, -14.1); A4 r 1.75 centre (26.4, -13.6) between (25.6, -12.044) and (25.6, -15.156) reference
  constraints: 6 end point, 4 point on circle, 2 centre point, 1 coincident, 1 concentric, 1 equal radius, 1 midpoint, 1 parallel, 1 perpendicular
  dimensions: "d239" = 0.5 radius of A2
revolve "Revolution4" stored, may be unused: angle "d240" = 90 deg
revolve "Revolution5" stored, may be unused: angle "d241" = 90 deg
workplane "Work Plane5"
sketch "Sketch29"
  geometry: L1 (24.5, -38)-(22.5, -38); L2 (18.8, -37.5)-(16.8, -37.5); L3 (13.5, -37.5)-(11.5, -37.5); L4 (24, -28.5)-(22, -28.5); L5 (37, 9.3)-(37, -55.8) reference; L6 (88.8, 6)-(-14.8, 6) reference; L7 (12.5, -43.3)-(12.5, -30) reference; A1 r 1 centre (23.5, -38) between (24.5, -38) and (22.5, -38); A2 r 1 centre (17.8, -37.5) between (18.8, -37.5) and (16.8, -37.5); A3 r 1 centre (12.5, -37.5) between (13.5, -37.5) and (11.5, -37.5); A4 r 1 centre (23, -28.5) between (24, -28.5) and (22, -28.5); 2 further points
  constraints: 8 end point, 8 point on circle, 6 midpoint, 4 centre point, 3 equal length, 3 equal radius, 1 horizontal, 1 horizontal alignment, 1 point on line
  dimensions: "d243" = 2 diameter of A1; "d244" = 34.5 distance from line of L6 A4.centre; "d245" = 44 distance from line of L6 A1.centre; "d246" = 43.5 distance from line of L6 A2.centre; "d247" = 5.3 distance of A3.centre A2.centre; "d248" = 11 horizontal distance of A3.centre A1.centre; "d249" = 10.5 horizontal distance of A4.centre A3.centre
revolve "Revolution6" stored, may be unused: angle "d250" = 90 deg
revolve "Revolution7" stored, may be unused: angle "d251" = 90 deg
revolve "Revolution8" stored, may be unused: angle "d252" = 90 deg
sketch "Sketch30"
  geometry: L1 (-28.75, 18.85)-(-27.5, 17.6); L2 (-2.25, 18.85)-(-3.5, 17.6); L3 (-1, 18.85)-(-3.5, 18.85) reference; L4 (-27.5, 18.85)-(-30, 18.85) reference; L5 (-27.5, 18.85)-(-27.5, 16.15) reference; L6 (-3.5, 18.85)-(-3.5, 16.15) reference
  constraints: 4 end point, 2 midpoint, 2 point on line
  dimensions: "d253" = 45 deg angle of L4 L1; "d254" = 45 deg angle of L3 L2
extrude "Extrusion26" cut sketch "Sketch30" extent not by distance; stored distance "d255" = 0.2; taper "d256" = 0 deg
sketch "Sketch31"
  geometry: L1 (-15.5, 4.9)-(-18, 4.9) reference; L2 (0, 4.9)-(-2.5, 4.9) reference; L3 (-1.25, 4.9)-(-2.5, 3.65); L4 (-16.75, 4.9)-(-15.5, 3.65); L5 (-15.5, 4.9)-(-15.5, 2.9) reference; L6 (-2.5, 4.9)-(-2.5, 2.9) reference
  constraints: 4 end point, 2 midpoint, 2 point on line
  dimensions: "d257" = 45 deg angle of L2 L3; "d258" = 45 deg angle of L1 L4
extrude "Extrusion27" cut sketch "Sketch31" distance "d259" = 4; taper "d260" = 0 deg
sketch "Sketch32"
  geometry: L1 (0, 0)-(6, 0) reference; L2 (4.9, -2.9)-(1.1, -2.9) reference; L3 (5.1, -2.2)-(0.9, -2.2); L4 (0.9, -2.2)-(0.9, -0.6); L5 (0.9, -0.6)-(5.1, -0.6); L6 (5.1, -0.6)-(5.1, -2.2); 2 further points
  constraints: 8 end point, 2 midpoint, 2 parallel, 1 horizontal, 1 perpendicular, 1 vertical alignment
  dimensions: "d261" = 4.2 distance of L3.start L3.end; "d262" = 1.6 distance of L3.end L4.end; "d263" = 0.6 distance between parallel lines of L1 L5
extrude "Extrusion28" join sketch "Sketch32" distance "d264" = 0.3; taper "d265" = 0 deg
sketch "Sketch33"
  geometry: L1 (0, 4)-(0, 0) reference; L2 (-4, 6)-(-4, -5.3); L3 (-4, -5.3)-(-2, -5.3); L4 (-2, -5.3)-(-2, -3.3); L5 (-2, -3.3)-(-2.6, -3.3); L6 (-2.6, -3.3)-(-2, 0.969); L7 (-2, 0.969)-(-2, 4); L8 (-2, 4)-(0, 4); L9 (-4, 6)-(0, 6); L10 (0, 6)-(0, 4)
  constraints: 18 end point, 4 perpendicular, 3 parallel, 2 collinear
  dimensions: "d267" = 11.3 distance between parallel lines of L9 L3; "d268" = 2 distance between parallel lines of L9 L8; "d269" = 2 distance between parallel lines of L2 L4; "d270" = 4 distance of L2.start L9.end; "d271" = 2 distance of L3.end L4.end; "d272" = 0.6 distance of L4.end L5.end; "d273" = 82 deg angle of L5 L6
extrude "Extrusion29" join sketch "Sketch33" distance "d274" = 10; taper "d275" = 0 deg
sketch "Sketch34"
  geometry: L1 (0, -6)-(-4, -6) reference; L2 (0, -4)-(0, -6) reference; L3 (-2, -4)-(0, -4) reference; L4 (-2, -0.969)-(-2, -4) reference; L5 (-2.6, 3.3)-(-2, -0.969) reference; L6 (-2, 3.3)-(-2.6, 3.3) reference; L7 (-2, 5.3)-(-2, 3.3) reference; L8 (-4, 5.3)-(-2, 5.3) reference; L9 (-4, -6)-(-4, 5.3) reference; L10 (-4, -6)-(0, -6); L11 (0, -6)-(0, 5.3); L12 (0, 5.3)-(-4, 5.3); L13 (-4, 5.3)-(-4, -6)
  constraints: 8 end point, 2 collinear, 2 parallel, 1 horizontal, 1 perpendicular
extrude "Extrusion30" join sketch "Sketch34" stored distance "d276" = 10; taper "d277" = 0 deg
sketch "Sketch35"
  geometry: L1 (11.3, 0)-(11.3, -10) reference; L2 (0, -10)-(2.3, -10); L3 (2.3, -10)-(2.3, -2.5); L4 (2.3, -2.5)-(0, -2.5); L5 (0, -2.5)-(0, -10)
  constraints: 8 end point, 2 parallel, 1 horizontal, 1 perpendicular
  dimensions: "d278" = 7.5 distance of L4.end L2.start; "d279" = 9 distance between parallel lines of L1 L3
extrude "Extrusion31" cut sketch "Sketch35" stored distance "d280" = 10; taper "d281" = 0 deg
sketch "Sketch36"
  geometry: L1 (6, -3.3)-(6, 14.5) reference; L2 (13.3, 4)-(7.7, -3.3) reference; L3 (0, 18.46)-(0, -9.26) reference; L4 (-18.3, 0)-(64.3, 0) reference; L5 (6, 4.232)-(2, 7.3); L6 (2, 7.3)-(-2, 7.3); L7 (-2, 7.3)-(-6.3, 4.001); L8 (-6.3, 4.001)-(-6.3, -2.3); L9 (-6.3, -2.3)-(-6.5, -2.3); L10 (-6.5, -2.3)-(-6.5, -5.3); L11 (-6.5, -5.3)-(-4.5, -5.3); L12 (-4.5, 0)-(-4.5, -5.3); L13 (4.5, -3.3)-(4.5, 0); L14 (7.7, -3.3)-(6, -3.3) reference; L15 (4.5, -3.3)-(6, -3.3); L16 (6, 4.232)-(6, -3.3); A1 r 4.5 centre (0, 0) between (4.5, 0) and (-4.5, 0)
  constraints: 22 end point, 5 point on line, 2 collinear, 2 parallel, 2 perpendicular, 2 point on circle, 2 tangent, 2 vertical, 1 centre point, 1 other
  dimensions: "d283" = 4 distance of L5.end L6.end; "d284" = 12.6 distance between parallel lines of L11 L6; "d291" = 4.5 radius of A1; "d294" = 2 distance between parallel lines of L11 L15; "d295" = 3 distance of L9.end L10.end; "d297" = 0.2 distance between parallel lines of L10 L8; "d298" = 2 distance between parallel lines of L10 L12
extrude "Extrusion32" join sketch "Sketch36" distance "d289" = 7.7; taper "d290" = 0 deg
sketch "Sketch37"
  geometry: L1 (-6, 4.232)-(-2, 7.3) reference; L2 (2, 7.3)-(6.3, 4.001) reference; L3 (-2, 7.3)-(2, 7.3) reference; L4 (-6, 4.232)-(-6, 14.5) reference; L5 (12.5, 12.5)-(12.5, 9.607) reference; L6 (-6, 12.5)-(12.5, 12.5) reference; L7 (6.3, 4.001)-(6.3, 12.5); 2 further points; 1 other entity
  constraints: 2 end point, 1 perpendicular, 1 point on line, 2 other
extrude "Extrusion33" join sketch "Sketch37" distance "d299" = 2.2; taper "d300" = 0 deg
sketch "Sketch38"
  geometry: L1 (9.5, 76.5)-(9.5, 69) reference; L2 (-4.5, 76.5)-(9.5, 76.5); L3 (9.5, 76.5)-(9.5, 73.5); L4 (9.5, 73.5)-(-4.5, 73.5); L5 (-4.5, 73.5)-(-4.5, 76.5)
  constraints: 8 end point, 2 parallel, 1 horizontal, 1 perpendicular, 1 point on line
  dimensions: "d301" = 3 distance of L4.end L2.start
extrude "Extrusion34" cut sketch "Sketch38" distance "d302" = 0.5; taper "d303" = 0 deg
chamfer "Chamfer6" distance "d304" = 0.6; stored, may be unused: second distance "d305" = 2, angle "d306" = 30 deg
sketch "Sketch39"
  geometry: L1 (2, 4.5)-(1.5, 4.5) reference; L2 (1.5, 4.5)-(1.5, 7.5) reference; L3 (1.5, 7.5)-(0, 7.5) reference; L4 (0, 0)-(0, 7.5) reference; L5 (2, 0)-(0, 0) reference; L6 (2, 4.5)-(2, 0) reference; L7 (0, 0)-(66, 0); L8 (66, 0)-(66, 9.6); L9 (66, 9.6)-(0, 9.6); L10 (0, 9.6)-(0, 0); L11 (66, 0)-(66, 7.5) reference
  constraints: 8 end point, 2 parallel, 1 collinear, 1 horizontal, 1 perpendicular
  dimensions: "d307" = 9.6 distance of L7.end L8.end
extrude "Extrusion35" join sketch "Sketch39" stored distance "d308" = 2; taper "d309" = 0 deg
chamfer "Chamfer7" distance "d310" = 1; stored, may be unused: second distance "d311" = 2, angle "d312" = 30 deg
sketch "Sketch40"
  geometry: L1 (-66, 9.6)-(0, 9.6) reference; L2 (-33, 29.42)-(-33, -109.32) reference; L3 (2, -25.5)-(2, -34.5) reference; L4 (-53, 7.6)-(-57, 7.6); L5 (-57, 7.6)-(-57, 8.6); L6 (-57, 8.6)-(-53, 8.6); L7 (-53, 8.6)-(-53, 7.6); L8 (-9, 7.6)-(-13, 7.6); L9 (-13, 7.6)-(-13, 8.6); L10 (-13, 8.6)-(-9, 8.6); L11 (-9, 8.6)-(-9, 7.6)
  constraints: 16 end point, 4 parallel, 2 collinear, 2 horizontal, 2 perpendicular, 2 other
  dimensions: "d313" = 1 distance between parallel lines of L8 L10; "d314" = 4 distance of L9.end L10.end; "d315" = 48 distance of L5.end L10.end; "d316" = 1 distance between parallel lines of L1 L6
extrude "Extrusion36" cut sketch "Sketch40" extent not by distance; stored distance "d317" = 2; taper "d318" = 0 deg
sketch "Sketch41"
  geometry: L1 (-52.5, 14.5)-(-6, 14.5) reference; L2 (-21.9, 4)-(-50, 4) reference; L3 (-13.3, 4)-(-14.8, 4); L4 (-14.8, 4)-(-14.8, 14.5); L5 (-14.8, 14.5)-(-13.3, 14.5); L6 (-13.3, 14.5)-(-13.3, 4); L7 (-40.8, 4)-(-39.3, 4); L8 (-39.3, 4)-(-39.3, 14.5); L9 (-39.3, 14.5)-(-40.8, 14.5); L10 (-40.8, 14.5)-(-40.8, 4)
  constraints: 16 end point, 4 parallel, 3 point on line, 2 horizontal, 2 perpendicular
  dimensions: "d319" = 1.5 distance between parallel lines of L8 L10; "d320" = 1.5 distance between parallel lines of L6 L4; "d321" = 24.5 distance between parallel lines of L8 L4
extrude "Extrusion37" join sketch "Sketch41" distance "d322" = 1; taper "d323" = 0 deg
sketch "Sketch42"
  geometry: L1 (0, 0)-(18.5, 0) reference; L2 (18.5, 0)-(18.5, 24.5) reference; L3 (18.5, 11.5)-(15.5, 11.5); L4 (15.5, 11.5)-(15.5, 13.5); L5 (15.5, 13.5)-(18.5, 13.5); L6 (18.5, 13.5)-(18.5, 11.5); L7 (18.5, 15.9)-(15.5, 15.9); L8 (15.5, 15.9)-(15.5, 19.7); L9 (15.5, 19.7)-(18.5, 19.7); L10 (18.5, 19.7)-(18.5, 15.9)
  constraints: 16 end point, 4 parallel, 2 horizontal, 2 perpendicular, 2 point on line, 1 collinear
  dimensions: "d324" = 11.5 distance between parallel lines of L3 L1; "d325" = 2.4 distance between parallel lines of L7 L5; "d326" = 2 distance of L3.end L4.end; "d327" = 3.8 distance of L7.end L8.end; "d328" = 3 distance of L8.end L9.end
extrude "Extrusion38" join sketch "Sketch42" distance "d329" = 0.01; taper "d330" = 0 deg
sketch "Sketch43"
  geometry: L1 (15.5, 13.5)-(18.5, 13.5) reference; L2 (18.5, 13.5)-(18.5, 15.9) reference; L3 (18.5, 15.9)-(15.5, 15.9) reference; L4 (17, 15.9)-(14, 15.9); L5 (14, 15.9)-(14, 13.5); L6 (14, 13.5)-(17, 13.5); L7 (17, 13.5)-(17, 15.9)
  constraints: 8 end point, 2 parallel, 1 collinear, 1 horizontal, 1 midpoint, 1 perpendicular
  dimensions: "d343" = 3 distance of L4.start L4.end; "d344" = 1.5 distance between parallel lines of L2 L7
extrude "Extrusion39" cut sketch "Sketch43" distance "d345" = 1; taper "d346" = 0 deg
sketch "Sketch44"
  geometry: L1 (0, 0)-(2, 0) reference; L2 (0, -2.3)-(0, 0) reference; L3 (0, -2.3)-(2, -2.3) reference; L4 (2, 0)-(2, 0.5); L5 (2, 0.5)-(9.3, 0.5); L6 (9.3, 0.5)-(9.3, 3); L7 (9.3, 3)-(3, 5.5); L8 (3, 5.5)-(-3.5, 5.5); L9 (-3.5, 5.5)-(-3.5, 0); L10 (-3.5, 0)-(0, 0); L11 (2, 0)-(0, 0)
  constraints: 16 end point, 4 parallel, 2 perpendicular, 1 collinear
  dimensions: "d347" = 5.5 distance of L8.end L9.end; "d349" = 12.8 distance between parallel lines of L6 L9; "d350" = 6.5 distance of L7.end L8.end; "d351" = 0.5 distance between parallel lines of L1 L5; "d352" = 2.5 distance of L5.end L6.end; "d353" = 3.5 distance between parallel lines of L9 L2
extrude "Extrusion40" join sketch "Sketch44" distance "d354" = 2; taper "d355" = 0 deg
sketch "Sketch45"
  geometry: L1 (16.5, 57.5)-(16.5, 66.1) reference; L2 (14.5, 64)-(1.5, 64) reference; L3 (14, 13.5)-(14, 15.9) reference; L4 (9, 52.7)-(9, 60.2); L5 (9, 60.2)-(15, 60.2); L6 (15, 60.2)-(15, 58.7); L7 (15, 58.7)-(9, 58.7); L8 (9, 52.7)-(10.3, 52.7); L9 (10.3, 52.7)-(10.3, 58.7)
  constraints: 12 end point, 3 parallel, 3 perpendicular, 2 point on line
  dimensions: "d356" = 1.5 distance between parallel lines of L5 L7; "d357" = 6 distance of L4.end L5.end; "d358" = 1.5 distance between parallel lines of L1 L6; "d359" = 3.8 distance between parallel lines of L2 L5; "d360" = 1.3 distance between parallel lines of L9 L4; "d361" = 7.5 distance from line of L5 L8.end
extrude "Extrusion41" join sketch "Sketch45" distance "d362" = 1.8; taper "d363" = 0 deg
extrude "Extrusion42" join sketch "Sketch45" distance "d364" = 3; taper "d365" = 0 deg
chamfer "Chamfer12" distance "d366" = 1; stored, may be unused: second distance "d367" = 2, angle "d368" = 60 deg
mirror "Mirror3"
sketch "Sketch46"
  geometry: L1 (-50, 4)-(-50, 9.5) reference; L2 (-52.5, 9.5)-(-50, 9.5); L3 (-50, 9.5)-(-50, 11.5); L4 (-50, 11.5)-(-52.5, 11.5); L5 (-52.5, 11.5)-(-52.5, 9.5); L6 (-52.5, 11.5)-(-55.08, 11.5) reference
  constraints: 8 end point, 2 collinear, 2 parallel, 1 horizontal, 1 perpendicular
extrude "Extrusion43" cut sketch "Sketch46" stored distance "d369" = 3; taper "d370" = 0 deg
sketch "Sketch47"
  geometry: L1 (45.5, 0)-(74, 0) reference; L2 (74, 0)-(74, 3) reference; L3 (0, 0)-(45.5, 0) reference; L4 (71.5, 0)-(71.5, -0.5); L5 (72, -1)-(72.5, -1); L6 (72.5, -1)-(72.5, -2); L7 (72.5, -2)-(71.5, -2); L8 (70.5, -1)-(70.5, 0); L9 (71.5, 0)-(70.5, 0); A1 r 1 centre (71.5, -1) between (70.5, -1) and (71.5, -2); A2 r 0.5 centre (72, -0.5) between (71.5, -0.5) and (72, -1); 1 further point
  constraints: 12 end point, 4 perpendicular, 4 point on circle, 4 point on line, 4 tangent, 2 centre point, 1 horizontal, 1 parallel
  dimensions: "d371" = 1 distance of L5.end L6.end; "d372" = 1 distance between parallel lines of L8 L4; "d373" = 1.5 distance between parallel lines of L2 L6; "d374" = 2 distance between parallel lines of L6 L8; "d375" = 2 distance of point (70.5, -2) L8.end; "d376" = 1 radius of A1; "d377" = 0.5 radius of A2
extrude "Extrusion44" join sketch "Sketch47" stored distance "d378" = 3; taper "d379" = 0 deg
sketch "Sketch48"
  geometry: L1 (3, 24.5)-(3, 36.3) reference; L2 (19, 31)-(19, 28.5) reference; L3 (17, 28.5)-(19, 28.5) reference; L4 (17, 28.5)-(17, 31) reference; L5 (17, 31)-(19, 31) reference; L6 (3, 31.5)-(28.3, 31.5); L7 (28.3, 31.5)-(28.3, 2); L8 (28.3, 2)-(25.8, 2); L9 (3, 14)-(3, 31.5); L10 (3, 14)-(6.5, 12); L11 (6.5, 12)-(6.5, 10.5); L12 (6.5, 10.5)-(21, 10.5); L13 (21, 10.5)-(25.8, 2); L14 (18.5, 2)-(65, 2) reference; L15 (28.3, 31)-(28.3, 21) reference
  constraints: 16 end point, 3 parallel, 2 collinear, 2 perpendicular, 1 horizontal, 1 point on line
  dimensions: "d380" = 29.5 distance of L6.end L7.end; "d381" = 21 distance between parallel lines of L6 L12; "d382" = 17.5 distance of L9.start L6.start; "d384" = 18 distance from line of L9 L12.end; "d385" = 2.5 distance from line of L8.end L7; "d386" = 1.5 distance of L10.end L11.end; "d387" = 3.5 distance between parallel lines of L9 L11
extrude "Extrusion45" join sketch "Sketch48" distance "d388" = 10; taper "d389" = 0 deg
chamfer "Chamfer13" distance "d390" = 7.5; stored, may be unused: second distance "d391" = 2, angle "d392" = 23 deg
workplane "Work Plane8"
sketch "Sketch49"
  geometry: L1 (0, 0)-(18.1, 0) reference; L2 (-5.7, 10.4)-(0.607, 0.894); L3 (2.273, 0)-(9.9, 0); L4 (11.9, -2)-(11.9, -11.6); L5 (11.9, -11.6)-(12.9, -11.6); L6 (12.9, -11.6)-(12.9, -16.8); L7 (12.9, -16.8)-(1.9, -16.8); L8 (1.9, -16.8)-(1.9, -11.6); L9 (1.9, -11.6)-(2.9, -11.6); L10 (2.9, -11.6)-(2.9, -9.7); L11 (2.9, -9.7)-(1.4, -9.7); L12 (1.4, -9.7)-(-0.3, -8.2); L13 (-0.3, -8.2)-(-5.7, -8.2); L14 (-5.7, 10.4)-(-5.7, -8.2); L15 (-5.7, 22)-(-5.7, 13) reference; A1 r 2 centre (2.273, 2) between (0.607, 0.894) and (2.273, 0); A2 r 2 centre (9.9, -2) between (11.9, -2) and (9.9, 0); 2 further points
  constraints: 26 end point, 6 parallel, 5 point on line, 4 collinear, 4 point on circle, 4 tangent, 3 perpendicular, 2 centre point
  dimensions: "d394" = 11 distance of L6.end L7.end; "d395" = 9 distance between parallel lines of L10 L4; "d396" = 10.5 distance from line of L4 L11.end; "d397" = 12.2 distance from line of L4 L12.end; "d398" = 17.6 distance between parallel lines of L14 L4; "d399" = 5.2 distance of L5.end L6.end; "d400" = 16.8 distance between parallel lines of L1 L7; "d401" = 27.2 distance from line of L2.start L7; "d402" = 18.6 distance from line of L13 L2.start; "d403" = 9.7 distance between parallel lines of L11 L1; "d404" = 10.7 distance of point (1.2, 0) point (11.9, 0); "d405" = 2 radius of A1; "d406" = 2 radius of A2
extrude "Extrusion46" join sketch "Sketch49" stored distance "d407" = 10; taper "d408" = 0 deg
chamfer "Chamfer14" distance "d409" = 0.8; stored, may be unused: second distance "d410" = 2, angle "d411" = 30 deg
sketch "Sketch50"
  geometry: L1 (34.4, 9.9)-(34.4, 4.7) reference; L2 (34.4, 4.7)-(23.4, 4.7) reference; L3 (35.4, 10.1)-(22.4, 10.1); L4 (22.4, 10.1)-(22.4, 11.1); L5 (22.4, 11.1)-(35.4, 11.1); L6 (35.4, 11.1)-(35.4, 10.1); L7 (35.4, 10.1)-(37.4, 10.1); L8 (37.4, 10.1)-(37.4, 4.7); L9 (37.4, 4.7)-(35.4, 4.7); L10 (35.4, 4.7)-(35.4, 10.1); L11 (22.4, 10.1)-(20.4, 10.1); L12 (20.4, 10.1)-(20.4, 4.7); L13 (20.4, 4.7)-(22.4, 4.7); L14 (22.4, 4.7)-(22.4, 10.1); L15 (35.4, 10.1)-(34.4, 10.1); L16 (34.4, 10.1)-(34.4, 4.7); L17 (34.4, 4.7)-(35.4, 4.7); L18 (35.4, 4.7)-(35.4, 10.1); L19 (22.4, 10.1)-(23.4, 10.1); L20 (23.4, 10.1)-(23.4, 4.7); L21 (23.4, 4.7)-(22.4, 4.7); L22 (22.4, 4.7)-(22.4, 10.1); L23 (28.9, 22.648)-(28.9, -8.257); 1 further point
  constraints: 42 end point, 11 parallel, 7 collinear, 5 horizontal, 5 perpendicular, 1 midpoint, 1 point on line, 1 other
  dimensions: "d413" = 13 distance between parallel lines of L22 L10; "d414" = 17 distance between parallel lines of L12 L8; "d415" = 5.4 distance of L7.end L8.end; "d416" = 6.4 distance between parallel lines of L5 L9
extrude "Extrusion47" join sketch "Sketch50" distance "d418" = 1; taper "d419" = 0 deg
extrude "Extrusion48" join sketch "Sketch50" distance "d420" = 2; taper "d421" = 0 deg
sketch "Sketch51"
  geometry: L1 (21.9, -0.5)-(17.2, -0.5) reference; L2 (37.4, 4.7)-(20.4, 4.7); L3 (20.4, 4.7)-(20.4, -0.5); L4 (20.4, -0.5)-(37.4, -0.5); L5 (37.4, -0.5)-(37.4, 4.7); L6 (20.4, 4.7)-(20.4, 10.1) reference
  constraints: 8 end point, 2 parallel, 1 collinear, 1 horizontal, 1 perpendicular, 1 point on line
extrude "Extrusion49" cut sketch "Sketch51" stored distance "d422" = 2; taper "d423" = 0 deg
sketch "Sketch52"
  geometry: L1 (0, 11)-(-2.4, 11); L2 (-2.4, 11)-(-2.4, -1.747); L3 (-2.4, -1.747)-(0, -1.747); L4 (0, -1.747)-(0, 11); L5 (0, 11)-(-2.4, 11) reference; L6 (0, 11)-(0, 0) reference; L7 (0, -1.747)-(-2.4, -1.747) reference; L8 (-2.4, -15.8)-(-2.4, -1.747) reference
  constraints: 8 end point, 4 collinear, 2 parallel, 1 horizontal, 1 perpendicular
extrude "Extrusion50" cut sketch "Sketch52" stored distance "d424" = 2; taper "d425" = 0 deg
sketch "Sketch53"
  geometry: L1 (4.416, 13.2)-(4.416, -3.8) reference; L2 (0, 9.4)-(0, 0) reference; L3 (1.916, 9.2)-(4.416, 9.2); L4 (4.416, 9.2)-(4.416, 0.2); L5 (4.416, 0.2)-(1.916, 0.2); L6 (0.916, 1.2)-(0.916, 8.2); L7 (1.916, 9.2)-(0.916, 8.2); L8 (0.916, 1.2)-(1.916, 0.2); 6 further points
  constraints: 12 end point, 7 point on line, 3 midpoint, 2 horizontal alignment, 2 parallel, 1 horizontal, 1 perpendicular, 1 vertical alignment
  dimensions: "d426" = 3.5 distance of point (0.916, 9.2) L3.end; "d427" = 9 distance of point (0.916, 0.2) point (0.916, 9.2); "d429" = 1 distance of L3.start point (0.916, 9.2); "d430" = 1 distance of L6.end point (0.916, 9.2) (derived)
extrude "Extrusion51" cut sketch "Sketch53" distance "d432" = 5; taper "d433" = 0 deg
sketch "Sketch54"
  geometry: L1 (3, 31.5)-(20.8, 31.5) reference; L2 (3, 14)-(3, 31.5) reference; L3 (20.8, 10.5)-(6.5, 10.5) reference; L4 (16.6, 27.5)-(10.1, 27.5); L5 (10.1, 27.5)-(10.1, 25.8); L6 (10.1, 25.8)-(9, 25.8); L7 (9, 25.8)-(9, 24); L8 (9, 24)-(13.3, 24); L9 (13.3, 24)-(13.3, 25); L10 (13.3, 25)-(16.6, 25); L11 (16.6, 25)-(16.6, 27.5); L12 (17.5, 18.5)-(14, 18.5); L13 (14, 18.5)-(14, 17); L14 (14, 17)-(9.5, 17); L15 (9.5, 17)-(9.5, 14.5); L16 (9.5, 14.5)-(16.5, 14.5); L17 (16.5, 14.5)-(16.5, 16); L18 (16.5, 16)-(17.5, 16); L19 (17.5, 16)-(17.5, 18.5)
  constraints: 32 end point, 13 parallel, 3 perpendicular
  dimensions: "d434" = 2.5 distance of L10.end L4.start; "d435" = 3.5 distance between parallel lines of L8 L4; "d436" = 6.5 distance of L4.start L4.end; "d437" = 7.6 distance between parallel lines of L7 L11; "d438" = 4.3 distance of L7.end L8.end; "d439" = 7 distance of L15.end L16.end; "d440" = 3.5 distance of L12.start L12.end; "d441" = 1 distance between parallel lines of L19 L17; "d442" = 7 distance between parallel lines of L14 L8; "d443" = 4 distance between parallel lines of L1 L4; "d444" = 6 distance between parallel lines of L2 L7; "d445" = 1.8 distance of L6.end L7.end; "d446" = 6.5 distance between parallel lines of L2 L15; "d447" = 4 distance between parallel lines of L3 L16; "d448" = 2.5 distance of L18.end L12.start; "d449" = 4 distance between parallel lines of L12 L16
extrude "Extrusion52" cut sketch "Sketch54" distance "d450" = 1.5; taper "d451" = 0 deg
sketch "Sketch55" dims "d59" = 1.6 (= d57), "d197" = 1.8, "d441" = 1, "d458" = 7.5, "d465" = 0, "d472" = 1.5, "d576" = 1, "d599" = 0.5
  geometry: L1 (15.7, 26.85)-(11, 26.85); L2 (11, 25.65)-(15.7, 25.65); L3 (15.5, 16.35)-(10.5, 16.35); L4 (10.5, 15.15)-(15.5, 15.15); L5 (16.6, 27.5)-(16.6, 25) reference; L6 (9.5, 14.5)-(9.5, 17) reference; L7 (10.1, 27.5)-(16.6, 27.5) reference; L8 (16.5, 14.5)-(9.5, 14.5) reference; A1 r 0.6 centre (15.7, 26.25) between (15.7, 25.65) and (15.7, 26.85); A2 r 0.6 centre (11, 26.25) between (11, 26.85) and (11, 25.65); A3 r 0.6 centre (15.5, 15.75) between (15.5, 15.15) and (15.5, 16.35); A4 r 0.6 centre (10.5, 15.75) between (10.5, 16.35) and (10.5, 15.15); 7 further points
  constraints: 8 end point, 8 point on circle, 8 tangent, 7 midpoint, 4 centre point, 3 vertical alignment, 2 horizontal, 2 horizontal alignment, 2 parallel, 1 equal radius
  dimensions: "d452" = 5 distance of A4.centre A3.centre; "d453" = 4.7 distance of A2.centre A1.centre; "d454" = 1.2 distance between parallel lines of L2 L1
extrude "Extrusion53" join sketch "Sketch55" distance "d455" = 1; taper "d456" = 0 deg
